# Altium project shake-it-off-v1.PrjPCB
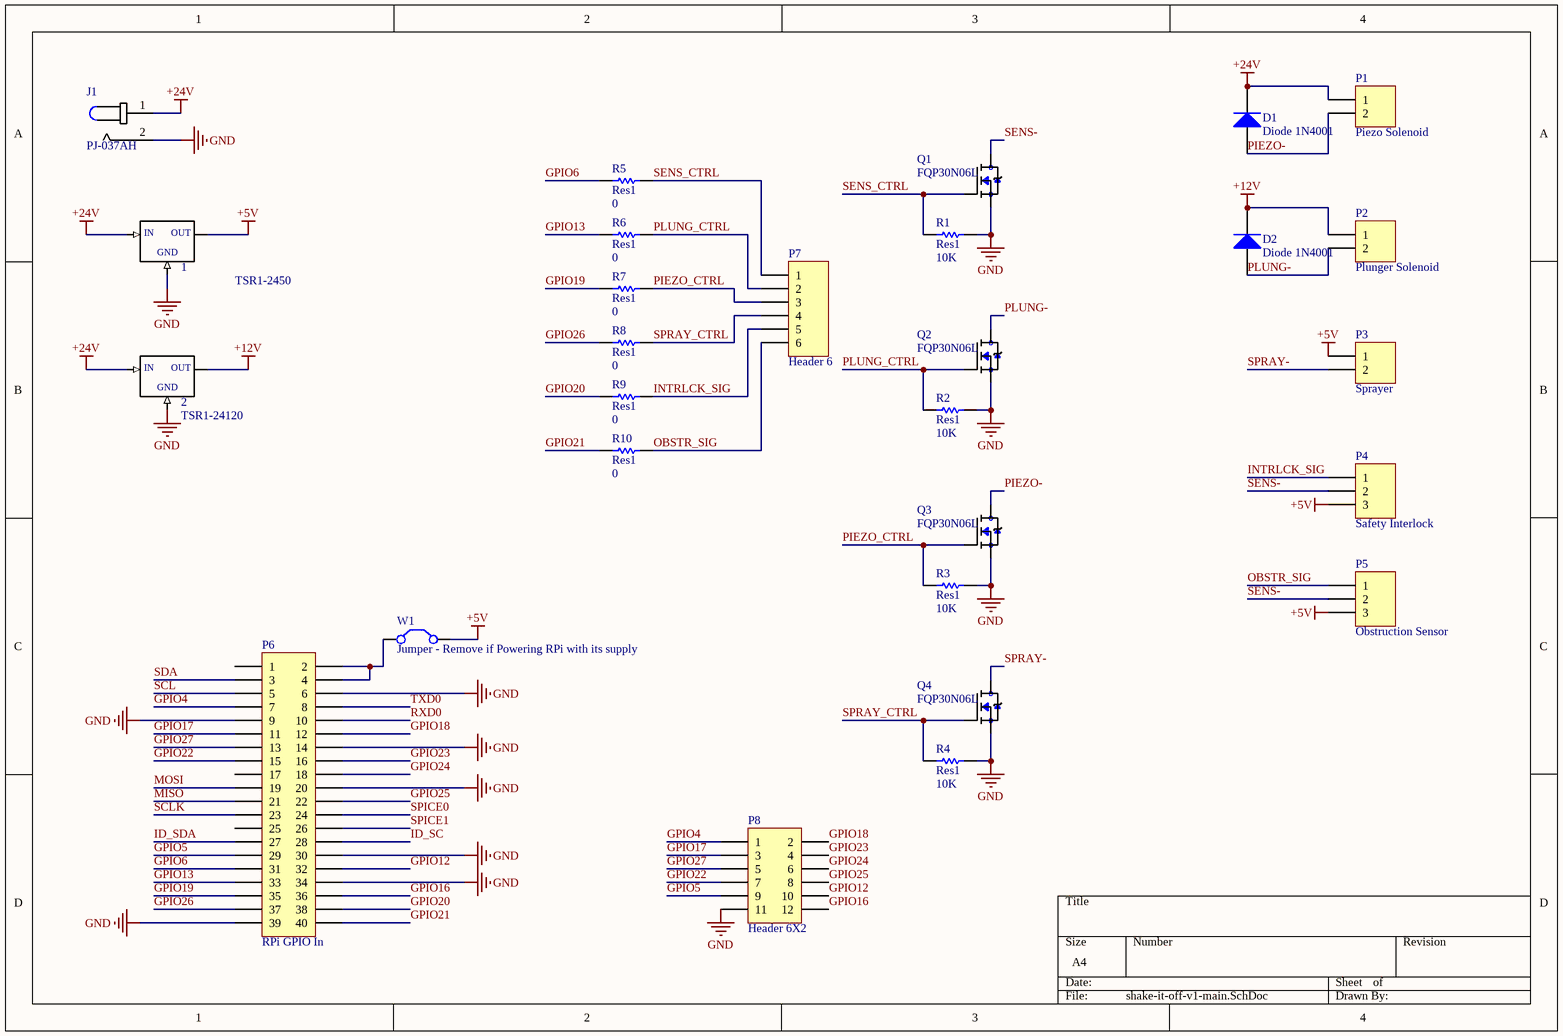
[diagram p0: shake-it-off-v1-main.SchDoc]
1 sheet, 28 parts. Net scope: global (net labels, ports and power ports of the same name join across sheets).
Board file: shake-it-off-v1-main.PcbDoc

## Sheet shake-it-off-v1-main.SchDoc
size A4

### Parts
1  TSR1-2450  [*TSR1-2450]
2  TSR1-24120  [*TSR1-2450]
D1  Diode 1N4001  [DO-41]
D2  Diode 1N4001  [DO-41]
J1  PJ-037AH  [*CUI_PJ-037AH]
P1  Piezo Solenoid  [HDR1X2]
P2  Plunger Solenoid  [HDR1X2]
P3  Sprayer  [HDR1X2]
P4  Safety Interlock  [HDR1X3]
P5  Obstruction Sensor  [HDR1X3]
P6  RPi GPIO In  [HDR2X20]
P7  Header 6  [HDR1X6]
P8  Header 6X2  [HDR2X6]
Q1  FQP30N06L  [*TO220V]
Q2  FQP30N06L  [*TO220V]
Q3  FQP30N06L  [*TO220V]
Q4  FQP30N06L  [*TO220V]
R1  Res1  value 10K  [0603]
R2  Res1  value 10K  [0603]
R3  Res1  value 10K  [0603]
R4  Res1  value 10K  [0603]
R5  Res1  value 0  [0603]
R6  Res1  value 0  [0603]
R7  Res1  value 0  [0603]
R8  Res1  value 0  [0603]
R9  Res1  value 0  [0603]
R10  Res1  value 0  [0603]
W1  Jumper - Remove if Powering RPi with its supply  [HDR1X2]

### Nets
+5V: 1.3(OUT) P3.1 P4.3 P5.3 W1.2(C2)
+12V: 2.3(OUT) D2.2(K) P2.1
+24V: 1.1(IN) 2.1(IN) D1.2(K) J1.1 P1.1
GND: 1.2(GND) 2.2(GND) J1.2 P6.6 P6.9 P6.14 P6.20 P6.30 P6.34 P6.39 P8.11 Q1.3(S) Q2.3(S) Q3.3(S) Q4.3(S) R1.1 R2.1 R3.1 R4.1
GPIO4: P6.7 P8.1
GPIO5: P6.29 P8.9
GPIO6: P6.31 R5.1
GPIO12: P6.32 P8.10
GPIO13: P6.33 R6.1
GPIO16: P6.36 P8.12
GPIO17: P6.11 P8.3
GPIO18: P6.12 P8.2
GPIO19: P6.35 R7.1
GPIO20: P6.38 R9.1
GPIO21: P6.40 R10.1
GPIO22: P6.15 P8.7
GPIO23: P6.16 P8.4
GPIO24: P6.18 P8.6
GPIO25: P6.22 P8.8
GPIO26: P6.37 R8.1
GPIO27: P6.13 P8.5
ID_SC: P6.28
ID_SDA: P6.27
INTRLCK_SIG: P4.1 P7.5 R9.2
MISO: P6.21
MOSI: P6.19
OBSTR_SIG: P5.1 P7.6 R10.2
PIEZO-: D1.1(A) P1.2 Q3.2(D)
PIEZO_CTRL: P7.3 Q3.1(G) R3.2 R7.2
PLUNG-: D2.1(A) P2.2 Q2.2(D)
PLUNG_CTRL: P7.2 Q2.1(G) R2.2 R6.2
RXD0: P6.10
SCL: P6.5
SCLK: P6.23
SDA: P6.3
SENS-: P4.2 P5.2 Q1.2(D)
SENS_CTRL: P7.1 Q1.1(G) R1.2 R5.2
SPICE0: P6.24
SPICE1: P6.26
SPRAY-: P3.2 Q4.2(D)
SPRAY_CTRL: P7.4 Q4.1(G) R4.2 R8.2
TXD0: P6.8
NetP6_2: P6.2 P6.4 W1.1(C1)

Not connected (* = marked no-connect by the designer): P6 1 17 25

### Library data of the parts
1 2 = TSR1-2450: Converter: DC/DC; Uin: 6.5Ã·36V; 5VDC; Iout: 1A; SIP3; Eff; MF: Traco Power
D1 D2 = Diode 1N4001: 1 Amp General Purpose Rectifier
J1 = PJ-037AH: 2.0 mm Center Pin, 5.0 A, Right Angle, Through Hole, Dc Power Jack Connector; MF: CUI Inc.
P1-P3 = Header 2: Header, 2-Pin
P4 P5 = Header 3: Header, 3-Pin
P6 = Header 20X2: Header, 20-Pin, Dual row
P7 = Header 6: Header, 6-Pin
P8 = Header 6X2: Header, 6-Pin, Dual row
Q1-Q4 = FQP30N06L: MOSFET Transistor, N Channel, 32 A, 60 V, 27 mohm, 10 V, 2.5 V; MF: ON Semiconductor
R1-R10 = Res1: Resistor
W1 = Jumper: Jumper Wire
